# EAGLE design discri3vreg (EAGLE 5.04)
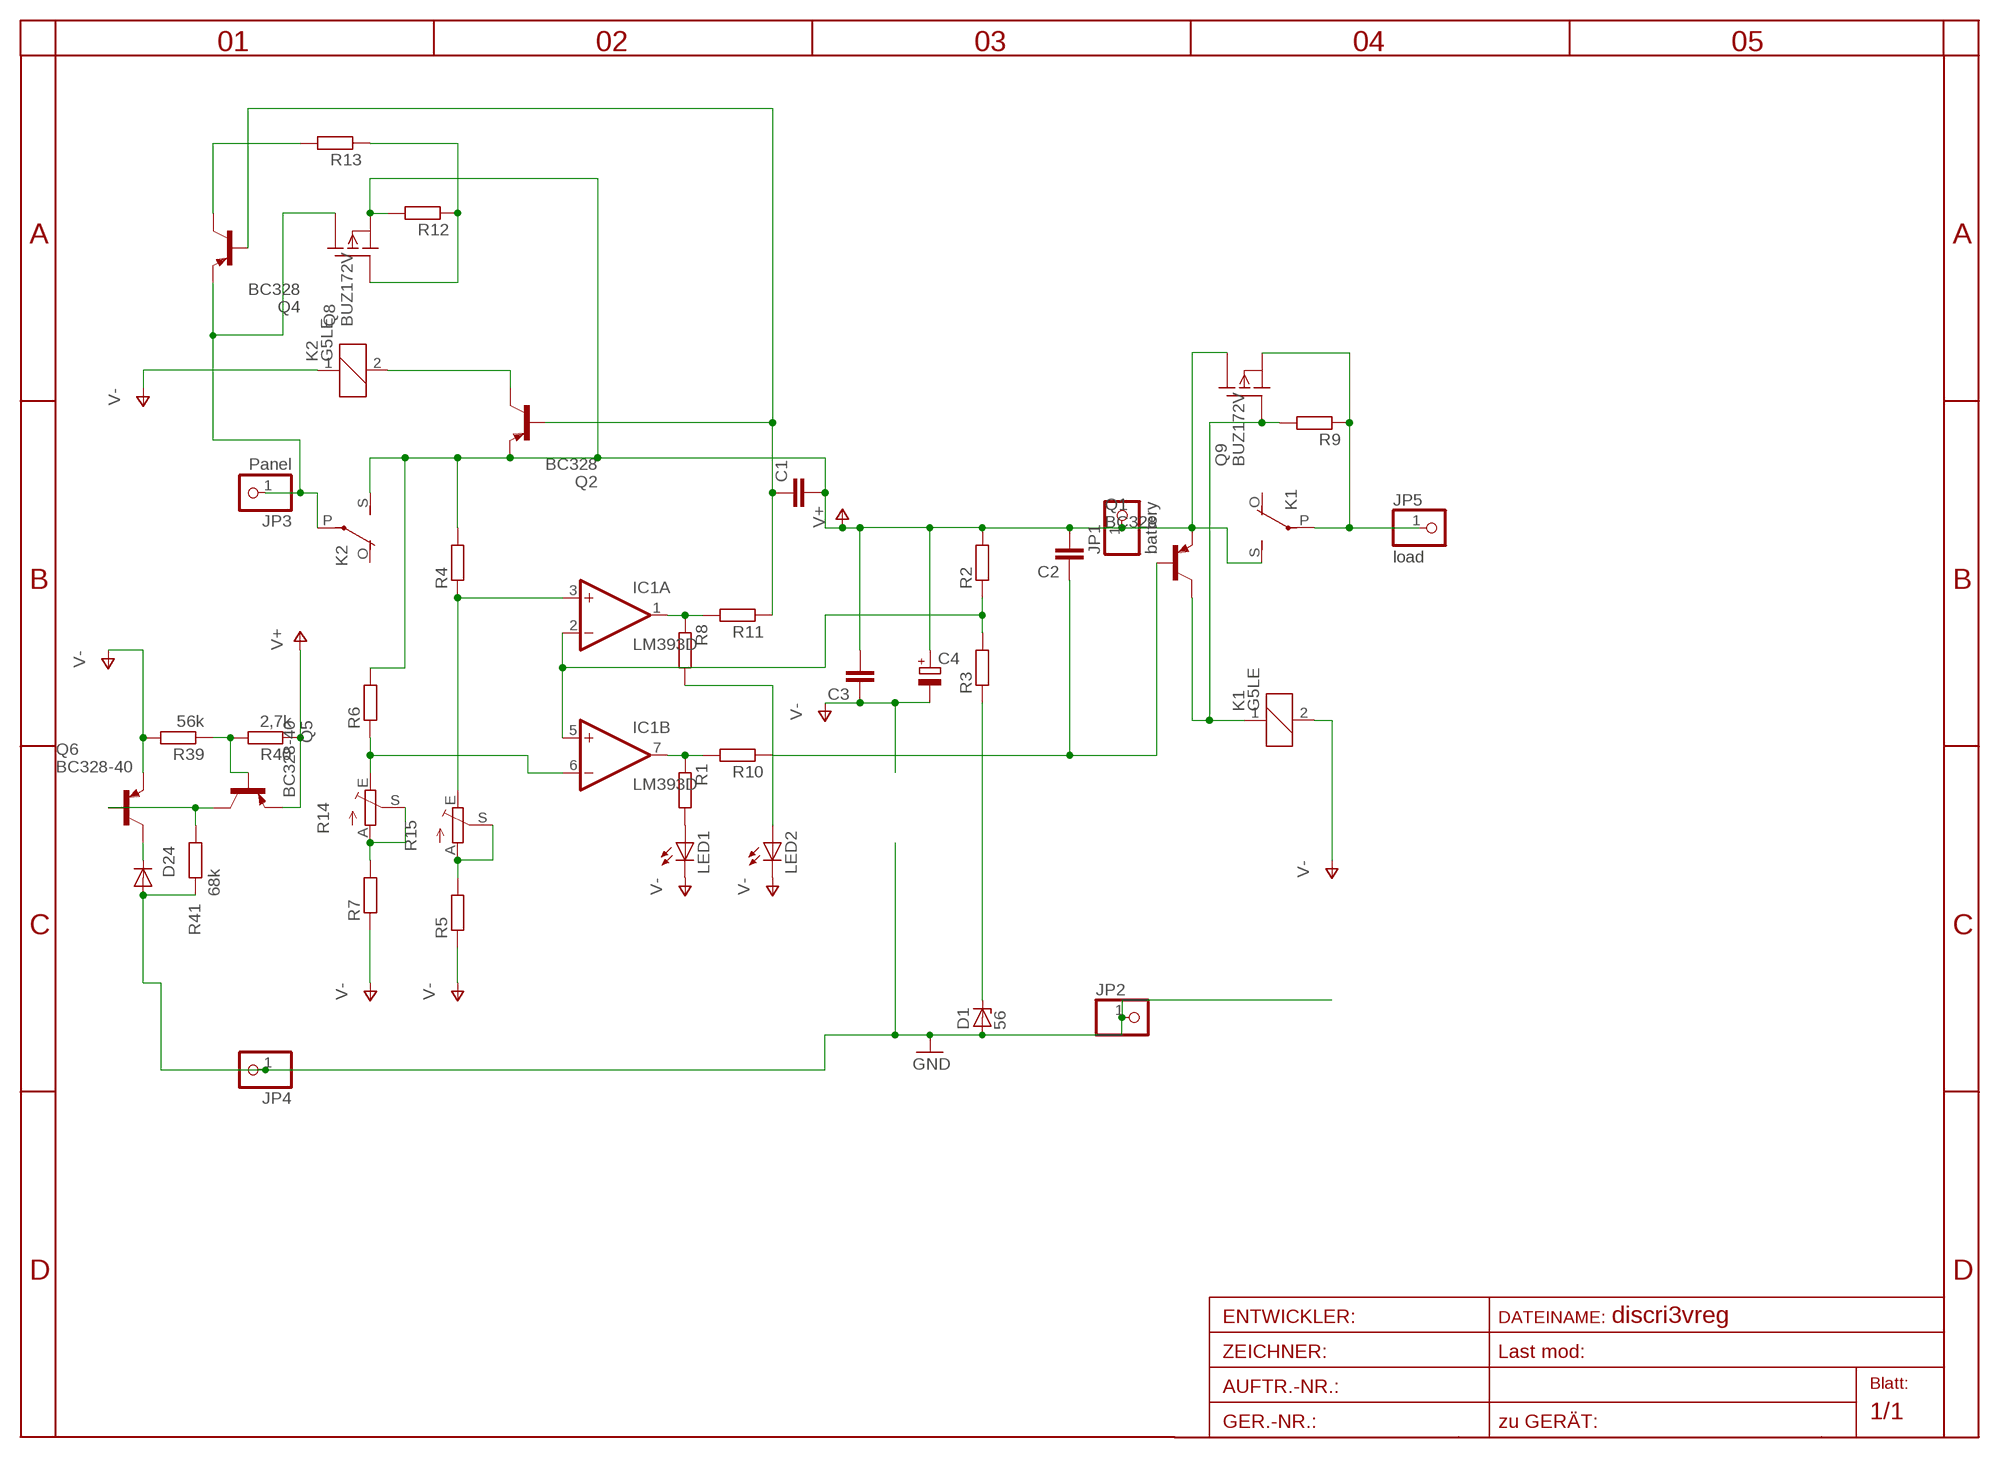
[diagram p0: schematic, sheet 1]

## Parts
C1  C-EU025-025X050  [C025-025X050]
C2  C-EU025-025X050  [C025-025X050]
C3  C-EU025-025X050  [C025-025X050]
C4  CPOL-EU5-13  [2,5-5-FLAT]
D1  56  ZENER-DIODEDO35Z10  [DO35Z10]
D24  Z20  DIODE-D-7.5  [D-7.5]
IC1  LM393D  [SO08]
JP1  battery  PINHD-1X1  [1X01]
JP2  PINHD-1X1  [1X01]
JP3  Panel  PINHD-1X1  [1X01]
JP4  PINHD-1X1  [1X01]
JP5  load  PINHD-1X1  [1X01]
K1  G5LE  [G5LE]
K2  G5LE  [G5LE]
LED1  LED3MM  [LED3MM]
LED2  LED3MM  [LED3MM]
Q1  BC328  [TO92-EBC]
Q2  BC328  [TO92-EBC]
Q4  BC328  [TO92-EBC]
Q5  BC328-40  [TO92-EBC]
Q6  BC328-40  [TO92-EBC]
Q8  BUZ172V  [TO220V]
Q9  BUZ172V  [TO220V]
R1  R-EU_0207/15  [0207/15]
R2  R-EU_0204/7  [0204/7]
R3  R-EU_0204/7  [0204/7]
R4  R-EU_0204/7  [0204/7]
R5  R-EU_0204/7  [0204/7]
R6  R-EU_0204/7  [0204/7]
R7  R-EU_0204/7  [0204/7]
R8  R-EU_0207/20  [0207/20]
R9  R-EU_0204/5  [0204/5]
R10  R-EU_0207/15  [0207/15]
R11  R-EU_0204/7  [0204/7]
R12  R-EU_0204/7  [0204/7]
R13  R-EU_0204/7  [0204/7]
R14  TRIM_EU-CA6V  [CA6V]
R15  TRIM_EU-CA6V  [CA6V]
R39  56k  R-EU_0204/7  [0204/7]
R40  2,7k  R-EU_0204/2V  [0204V]
R41  68k  R-EU_0207/10  [0207/10]

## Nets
GND: D1.A D24.A JP2.1 JP4.1 R41.2
LOAD: JP5.1 K1.P(2:P) Q9.3(S) R9.1
N$1: D1.C R3.1
N$2: IC1.6(B:-IN) R6.1 R14.E
N$3: R7.2 R14.A R14.S
N$4: IC1.2(A:-IN) IC1.5(B:+IN) R2.1 R3.2
N$5: K1.1 Q1.C Q9.1(G) R9.2
N$6: LED1.A R1.2
N$7: LED2.A R8.2
N$8: K2.2 Q2.C
N$11: R5.2 R15.A R15.S
N$12: IC1.3(A:+IN) R4.1 R15.E
N$13: D24.C Q6.C
N$14: IC1.1(A:OUT) R8.1 R11.2
N$15: IC1.7(B:OUT) R1.1 R10.2
N$16: C1.1 Q2.B Q4.B R11.1
N$17: C2.1 Q1.B R10.1
N$19: Q8.1(G) R12.1 R13.1
N$20: Q4.C R13.2
N$38: Q5.C Q6.B R41.1
N$41: Q5.B R39.1 R40.2
PANEL: JP3.1 K2.P(2:P) Q4.E Q8.2(D)
V+: C1.2 C2.2 C3.2 C4.+ JP1.1 K1.S(2:S) K2.S(2:S) Q1.E Q2.E Q5.E Q8.3(S) Q9.2(D) R2.2 R4.2 R6.2 R12.2 R40.1
V-: C3.1 C4.- K1.2 K2.1 LED1.K(C) LED2.K(C) Q6.E R5.1 R7.1 R39.2
Unconnected: K1.O(2:O) K2.O(2:O)

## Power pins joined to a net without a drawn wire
V+: IC1.8(P:V+)
V-: IC1.4(P:V-)

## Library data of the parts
C1-C3 = rcl-2:C-EU: CAPACITOR, European symbol
C4 = rcl-2:CPOL-EU: POLARIZED CAPACITOR, European symbol
D1 = diode-1:ZENER-DIODE: Z-Diode
D24 = diode-1:DIODE-: DIODE
IC1 = linear:LM393: COMPARATOR
JP1-JP5 = pinhead:PINHD-1X1: PIN HEADER
K1 K2 = relay2:G5LE: RELAY 1 x switch, 10 A/120 V AC, 8 A/30 V DC, Omron
LED1 LED2 = led:LED: LED
Q1 Q2 Q4-Q6 = transistor-pnp:BC328*: PNP Transistror
Q8 Q9 = transistor-fet:BUZ172: P-Channel Enhancement MOSFET -100V; -5A; 0,8Ohm
R1-R13 R39-R41 = rcl-2:R-EU_: RESISTOR, European symbol
R14 R15 = pot:TRIM_EU-: POTENTIOMETER

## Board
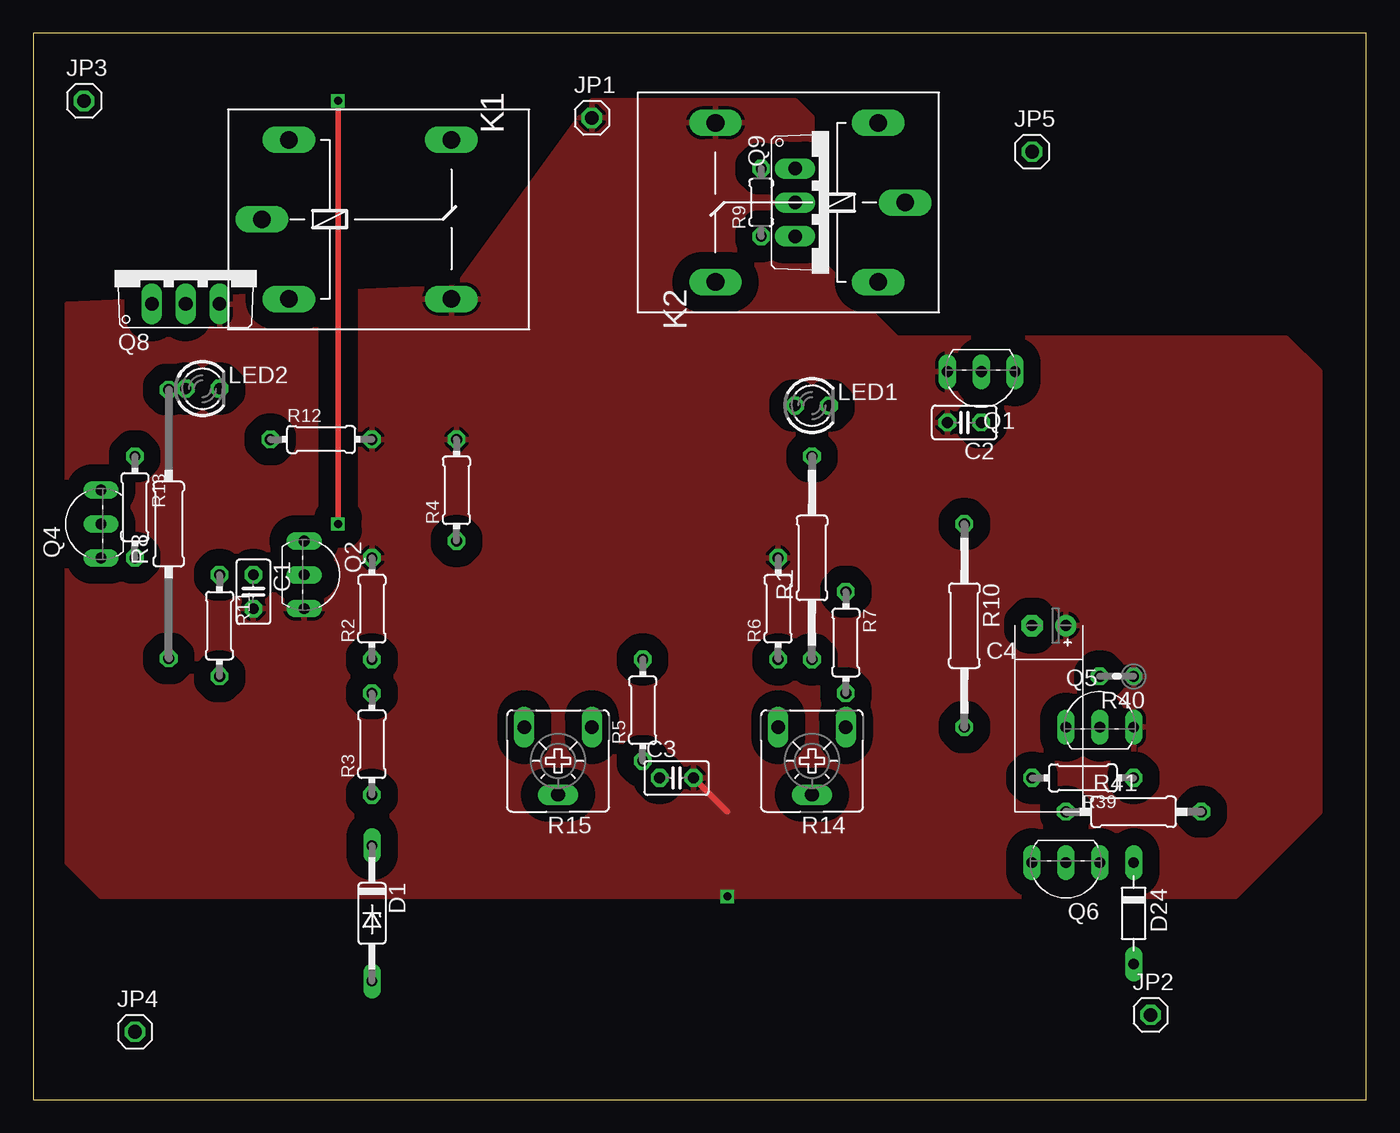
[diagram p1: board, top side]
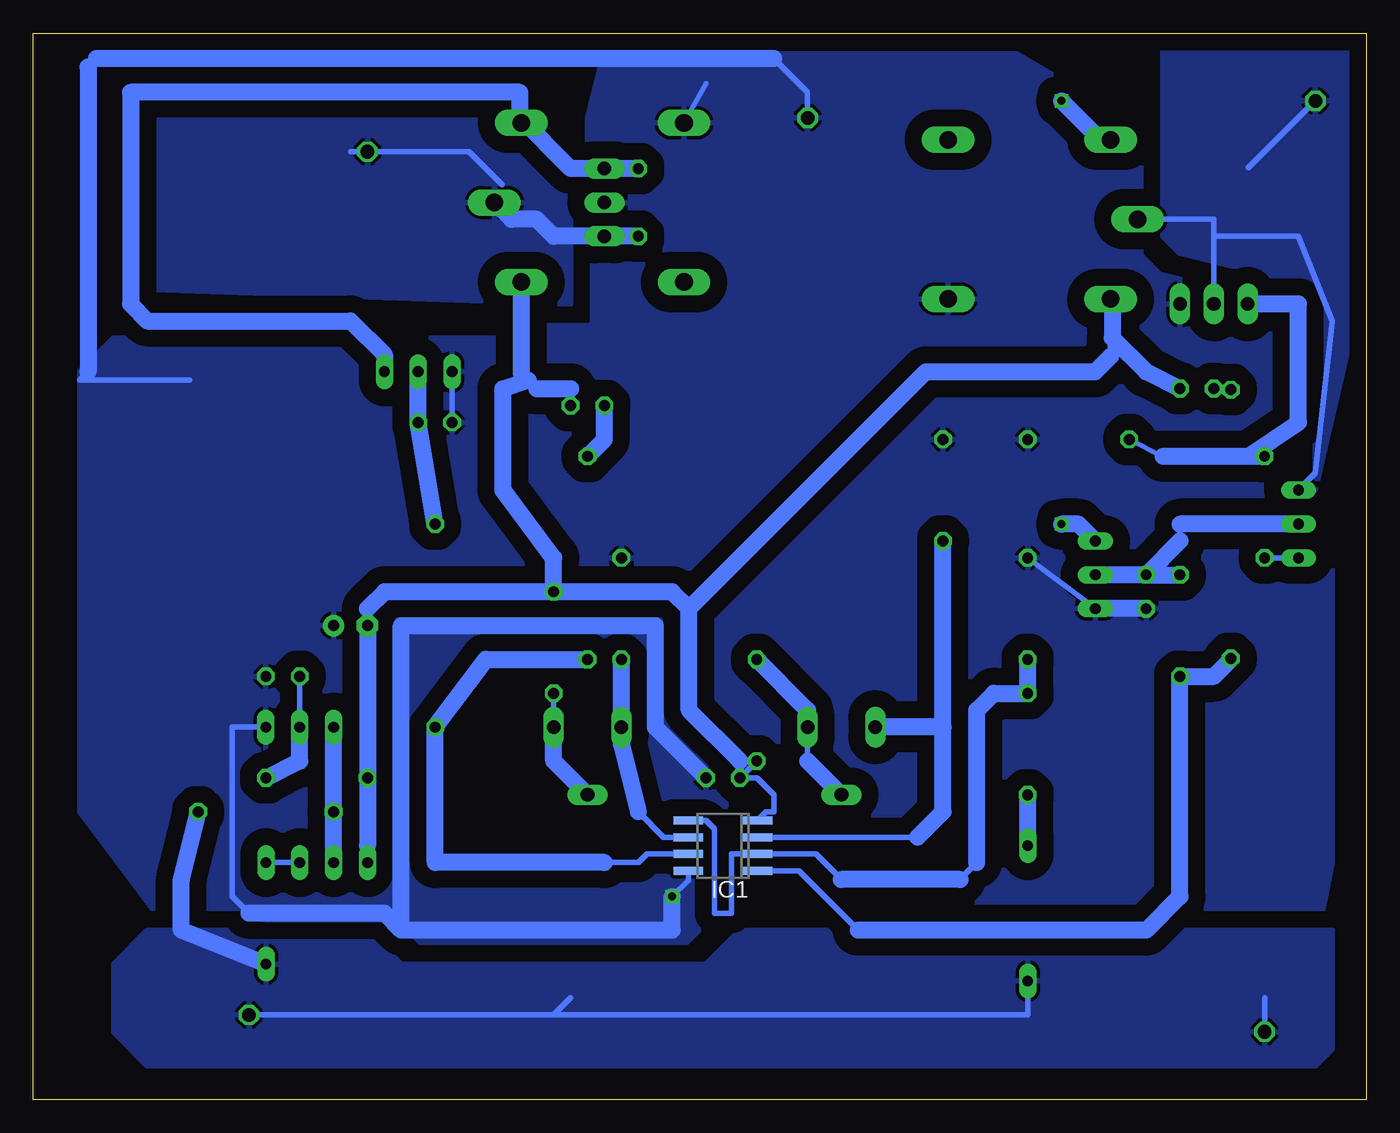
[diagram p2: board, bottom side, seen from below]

Size 100 x 80 mm. Coordinates in mm from the lower left corner, seen from the top.
Outline: 0,0 100,0 100,80 0,80 0,0
Copper layers (1*16): Top 0.035mm / dielectric 1.5mm / Bottom 0.035mm
Design rules "default": minimum track width 10mil, minimum drill 24mil, track to track 8mil, track to pad 8mil, pad to pad 8mil, via to via 8mil, smd to smd 8mil, copper to edge 40mil, drill to drill 8mil, minimum pad ring 10mil, minimum via ring 8mil, stop-mask expansion 4mil, vias tented up to drill 0mil, thermal gap 10mil

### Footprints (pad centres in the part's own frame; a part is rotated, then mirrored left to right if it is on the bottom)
C025-025X050 = drill 0.813 octagon: 1 -1.27,0; 2 1.27,0
2,5-5-FLAT = drill 0.813 pad 1.6 round: + -1.27,0 | drill 0.813 pad 1.6 octagon: - 1.27,0
DO35Z10 = drill 0.813 long: A 5.08,0; C -5.08,0
D-7.5 = drill 0.813 long: A 3.81,0; C -3.81,0
SO08 = smd 0.6 x 2.2: 1 -1.905,-2.6; 2 -0.635,-2.6; 3 0.635,-2.6; 4 1.905,-2.6; 5 1.905,2.6; 6 0.635,2.6; 7 -0.635,2.6; 8 -1.905,2.6
1X01 = drill 1.016 octagon: 1 0,0
G5LE = drill 1.321 long: 1 -7.493,-5.969; 2 -7.493,5.969; O 4.699,5.969; P -9.525,0; S 4.699,-5.969
LED3MM = drill 0.813 octagon: A -1.27,0; K 1.27,0
TO92-EBC = drill 0.813 long: B 0,-1.27; C -2.54,-1.27; E 2.54,-1.27
TO220V = drill 1.016 long: 1 -2.54,-2.54; 2 0,-2.54; 3 2.54,-2.54
0207/15 = drill 0.813 octagon: 1 -7.62,0; 2 7.62,0
0204/7 = drill 0.813 octagon: 1 -3.81,0; 2 3.81,0
0207/20 = drill 0.813 octagon: 1 -10.08,0; 2 10.08,0
0204/5 = drill 0.813 octagon: 1 -2.54,0; 2 2.54,0
CA6V = drill 1.016 long: A -2.54,-2.54; E 2.54,-2.54; S 0,2.54
0204V = drill 0.813 octagon: 1 -1.27,0; 2 1.27,0
0207/10 = drill 0.813 octagon: 1 -5.08,0; 2 5.08,0

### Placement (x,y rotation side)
C1  16.51,38.1 270 top
C2  69.85,50.8 180 top
C3  48.26,24.13 0 top
C4  76.2,35.56 180 top
D1  25.4,13.97 270 top
D24  82.55,13.97 270 top
IC1  48.26,19.05 90 bottom
JP1  41.91,73.66 0 top
JP2  83.82,6.35 0 top
JP3  3.81,74.93 0 top
JP4  7.62,5.08 0 top
JP5  74.93,71.12 0 top
K1  55.88,67.31 180 top
K2  26.67,66.04 0 top
LED1  58.42,52.07 0 top
LED2  12.7,53.34 0 top
Q1  71.12,53.34 180 top
Q2  21.59,39.37 270 top
Q4  3.81,43.18 90 top
Q5  80.01,29.21 0 top
Q6  77.47,16.51 180 top
Q8  11.43,62.23 0 top
Q9  59.69,67.31 270 top
R1  58.42,40.64 90 top
R2  25.4,36.83 90 top
R3  25.4,26.67 90 top
R4  31.75,45.72 90 top
R5  45.72,29.21 90 top
R6  55.88,36.83 90 top
R7  60.96,34.29 270 top
R8  10.16,43.18 90 top
R9  54.61,67.31 90 top
R10  69.85,35.56 270 top
R11  13.97,35.56 270 top
R12  21.59,49.53 0 top
R13  7.62,44.45 270 top
R14  58.42,25.4 180 top
R15  39.37,25.4 180 top
R39  78.74,24.13 180 top
R40  81.28,31.75 180 top
R41  82.55,21.59 0 top

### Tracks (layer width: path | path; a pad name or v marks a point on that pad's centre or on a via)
GND
  Bottom 0.406: 62.23,6.35 60.96,6.35 59.69,7.62 | 62.23,6.35 JP2.1 | D1.A 25.4,6.35 62.23,6.35 | JP4.1 7.62,7.62
  Bottom 1.27: D24.A 88.9,12.7 88.9,16.51 R41.2
  pour Bottom (isolate 1.27, rank 4): 2.54,12.7 46.99,12.7 49.53,10.16 72.39,10.16 74.93,12.7 91.44,12.7 93.98,10.16 93.98,5.08 91.44,2.54 3.81,2.54 2.54,3.81
LOAD
  Bottom 0.406: 64.83,68.64 67.31,71.12 JP5.1 76.2,71.12
  Bottom 1.27: K1.P 64.14,66.04 62.23,66.04 60.96,64.77 Q9.3 R9.1
  pour Bottom (isolate 1.27, rank 4): 59.69,76.2 62.23,78.74 93.98,78.74 96.52,76.2 96.52,60.96 59.69,59.69
N$1
  Bottom 1.27: D1.C R3.1
N$2
  Bottom 0.406: IC1.6 52.7,19.68 54.61,21.59 | 55.88,26.67 R14.E
  Bottom 1.27: R14.E R6.1 | 54.61,21.59 55.88,26.67
N$3
  Bottom 0.406: R14.A R7.2
  Bottom 1.27: R14.S 60.96,25.4 R14.A
N$4
  Bottom 0.406: 39.37,16.51 41.27,18.41 IC1.2 47.62,18.41 47.62,13.97 48.9,13.97 48.9,20.32 49.53,20.95 IC1.5 | 29.21,17.78 30.48,16.51
  Bottom 1.27: 30.48,16.51 39.37,16.51 | 29.21,17.78 29.21,29.21 27.94,30.48 R3.2 R2.1
N$5
  Bottom 1.27: Q1.C 73.66,55.88 76.2,58.42 91.44,58.42 92.71,59.69 92.71,75.56 63.5,75.56 63.5,73.66 | 63.5,73.66 59.69,69.85 Q9.1 R9.2 | 63.5,73.66 63.5,73.41 K1.1
N$6
  Bottom 1.27: R1.2 57.15,49.53 LED1.A
N$7
  Bottom 0.406: R8.2 LED2.A
N$8  (via drill 0.6)
  Top 0.406: v22.86,43.18 v22.86,74.93
  Bottom 0.406: 19.94,72.01 K2.2
  Bottom 1.27: v22.86,74.93 19.94,72.01 | v22.86,43.18 21.59,43.18 Q2.C
N$11
  Bottom 0.406: 41.91,25.4 R15.A 41.91,29.21
  Bottom 1.27: R15.S 41.91,25.4 | 41.91,29.21 R5.2
N$12
  Bottom 0.406: 33.66,19.68 IC1.3
  Bottom 1.27: 31.75,27.94 31.75,21.59 33.66,19.68 | 31.75,27.94 R4.1 | 31.75,27.94 R15.E
N$13
  Bottom 0.406: Q6.C D24.C
N$14
  Bottom 0.406: IC1.1 42.55,17.14 38.1,12.7 | 10.16,33.02 R8.1
  Bottom 1.27: 38.1,12.7 16.51,12.7 13.97,15.24 R11.2 11.43,31.75 10.16,33.02
N$15
  Bottom 0.406: IC1.7 53.98,18.41 54.61,17.78 57.15,17.78
  Bottom 1.27: 57.15,17.78 69.85,17.78 R10.2 66.04,33.02 R1.1
N$16
  Bottom 0.406: 13.97,43.18 13.97,41.91
  Bottom 1.27: Q4.B 13.97,43.18 | 13.97,41.91 C1.1 | C1.1 R11.1 | C1.1 Q2.B
N$17
  Bottom 1.27: R10.1 C2.1 Q1.B
N$19
  Bottom 0.406: 8.89,48.26 15.24,48.26 R12.1
  Bottom 1.27: 8.89,48.26 5.08,50.8 5.08,59.69 Q8.1 | R13.1 15.24,48.26
N$20
  Bottom 0.406: Q4.C R13.2
N$38
  Bottom 1.27: Q6.B R41.1 Q5.C
N$41
  Bottom 0.406: Q5.B R40.2
  Bottom 1.27: R39.1 80.01,25.4 Q5.B
PANEL
  Bottom 0.406: JP3.1 8.83,69.91 | Q4.E 3.81,46.99 2.54,58.42 5.08,64.77 11.43,64.77 | Q8.2 11.43,66.04 K2.P
  pour Bottom (isolate 1.27): 0,80.01 0,62.23 3.81,45.72 3.81,60.96 13.97,63.5 15.24,64.77 15.24,80.01
V+  (via drill 0.6)
  Top 0.406: C3.2 52.07,21.59
  Bottom 0.406: K1.S 49.53,76.2 | C2.2 Q1.E | Q2.E R2.2 | IC1.8 50.86,16.45 v52.07,15.24 | 83.82,13.97 85.09,15.24 85.09,27.94 Q5.E | JP1.1 41.91,75.56 44.45,78.11 | 95.25,78.11 95.89,77.47 | 95.89,54.61 96.52,53.98 88.27,53.98
  Bottom 1.27: C1.2 Q2.E | v52.07,15.24 52.07,12.7 72.39,12.7 | 83.82,13.97 73.66,13.97 72.39,12.7 | 44.45,78.11 95.25,78.11 | 95.89,77.47 95.89,54.61 | 72.39,12.7 72.39,35.56 53.34,35.56 53.34,27.94 C3.2
  pour Bottom (isolate 1.27, rank 5): 26.67,78.74 57.15,78.74 58.42,73.66 58.42,63.5 64.77,57.15 93.98,57.15 96.52,54.61 96.52,21.59 88.9,11.43 3.81,11.43 2.54,17.78 2.54,63.5 5.08,66.04
  pour Top (isolate 1.27, rank 5): 41.91,74.93 57.15,74.93 58.42,73.66 58.42,63.5 64.77,57.15 93.98,57.15 96.52,54.61 96.52,21.59 90.17,15.24 5.08,15.24 2.54,17.78 2.54,59.69 31.75,60.96
V-
  Bottom 0.406: 62.23,53.34 62.87,53.98 63.37,54.48 | 59.69,53.34 LED1.K | C3.1 45.72,24.13 44.45,22.86 44.45,21.59 45.02,21.59 IC1.4 | C3.1 R5.1 | C3.1 46.99,25.4 | 74.93,36.83 C4.- | 74.93,19.05 Q6.E | 19.05,59.94 K2.1 19.18,55.75
  Bottom 1.27: 63.37,54.48 K1.2 | 62.23,53.34 59.69,53.34 | 46.99,25.4 50.8,29.21 50.8,36.83 | 50.8,36.83 52.07,38.1 R7.1 | R7.1 73.66,38.1 74.93,36.83 | C4.- R39.2 74.93,19.05 | LED2.K 16.51,54.61 19.05,57.15 19.05,59.94 | 19.18,55.75 20.32,54.61 33.02,54.61 50.8,36.83 | R7.1 60.96,40.64 64.77,45.72 64.77,53.34 62.87,53.98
